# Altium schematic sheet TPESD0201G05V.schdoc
size 127 x 101 mm
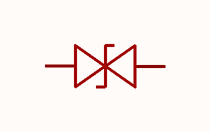
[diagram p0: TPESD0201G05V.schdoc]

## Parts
D?  tpesd0201g05v  [D0201-BI_2]  (value not drawn)

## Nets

Not connected (* = marked no-connect by the designer): D? 1 2

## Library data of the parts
D? = tpesd0201g05v: 极性:双向;反向截止电压(Vrwm):5V;钳位电压:40V;; Manufacturer: TECH PUBLIC(台舟); AddInBom: yes; Polarity: 双向; Reverse Stand-Off Voltage (Vrwm): 5V; Clamping Voltage: 40V; Reverse Leakage Current (Ir): 10nA; Number of Channels: 单路; level of protection: IEC 61000-4-2; Type: ESD; Junction Capacitance: 0.05pF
